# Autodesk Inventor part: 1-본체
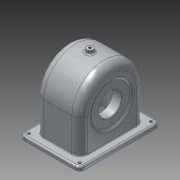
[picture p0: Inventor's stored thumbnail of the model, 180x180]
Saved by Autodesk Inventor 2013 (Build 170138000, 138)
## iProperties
Created: 2016-01
Part Number: 1-본체
Material: 알루미늄 6061
Document SubType Name: Modeling
Designer: Administrator
Density: 2.40731 g/cm^3
Mass: 671.571 g
Surface Area: 997.266 cm^2
Volume: 278.971 cm^3
Author: Administrator
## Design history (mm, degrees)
sketch "스케치1"
  geometry: L1 (-52, 70)-(52, 70); L2 (52, 70)-(52, -70); L3 (52, -70)-(-52, -70); L4 (-52, -70)-(-52, 70); 3 further points
  constraints: 8 end point, 2 midpoint, 2 parallel, 1 horizontal, 1 horizontal alignment, 1 perpendicular, 1 vertical alignment
  dimensions: "d0" = 104 distance between parallel lines of L2 L4; "d2" = 140 distance between parallel lines of L3 L1
extrude "돌출1" new body sketch "스케치1" distance "d3" = 7; taper "d4" = 0 deg
sketch "스케치3"
  geometry: L1 (-38.5, 56)-(38.5, 56); L2 (38.5, 56)-(38.5, -56); L3 (38.5, -56)-(-38.5, -56); L4 (-38.5, -56)-(-38.5, 56); 3 further points
  constraints: 8 end point, 2 midpoint, 2 parallel, 1 horizontal, 1 horizontal alignment, 1 perpendicular, 1 vertical alignment
  dimensions: "d5" = 77 distance between parallel lines of L2 L4; "d7" = 112 distance between parallel lines of L1 L3
extrude "돌출2" join sketch "스케치3" distance "d8" = 114; taper "d9" = 0 deg
fillet "모깎기1" dims "d10" = 56
feature "쉘1" dims "d11" = 7, "d12" = 5
sketch "스케치19"
  geometry: L1 (-38.5, 7)-(-38.5, 65) reference; L2 (-33.5, 0)-(-33.5, 65) reference; L3 (-38.5, 65)-(-38.5, 121) reference; L4 (-33.5, 65)-(-33.5, 116) reference; L5 (-38.5, 60)-(-19.5, 60); L6 (-19.5, 60)-(-19.5, 88); L7 (-19.5, 88)-(-38.5, 103.943); L8 (-52, 0)-(52, 0) reference; L9 (-38.5, 97.416)-(-35.5, 94.899); L10 (-35.5, 94.899)-(-35.5, 60); 1 further point
  constraints: 10 end point, 4 point on line, 3 perpendicular, 1 parallel
  dimensions: "d108" = 56 diameter of L6.end L5; "d111" = 50 deg angle of L7 L6; "d113" = 3 distance between parallel lines of L3 L10; "d114" = 5 distance between parallel lines of L7 L9; "d115" = 16 distance between parallel lines of L10 L6; "d116" = 60 distance from line of L8 L5.start
revolve "회전3" sketch "스케치19" stored, may be unused: angle "d117" = 90 deg
sketch "스케치20"
  geometry: L1 (-38.5, 65)-(-38.5, 121) reference; L2 (-38.5, 7)-(-38.5, 65) reference; L3 (-19.5, 32)-(-19.5, 88) reference; L4 (-33.5, 99.747)-(-19.5, 88) reference; L5 (-38.5, 60)-(-19.5, 60); L6 (-52, 0)-(52, 0) reference; L7 (-38.5, 97.416)-(-35.5, 94.899); L8 (-35.5, 94.899)-(-35.5, 60); 1 further point
  constraints: 6 end point, 3 point on line, 2 perpendicular, 1 midpoint, 1 parallel
  dimensions: "d118" = 60 distance between parallel lines of L6 L5; "d119" = 3 distance between parallel lines of L1 L8; "d120" = 5 distance between parallel lines of L4 L7
revolve "회전4" sketch "스케치20" stored, may be unused: angle "d121" = 90 deg
node "작업 평면1"
sketch "스케치10"
  geometry: C1 r 6 at (0, 0); 1 further point
  constraints: 1 centre point, 1 coincident
  dimensions: "d32" = 12 diameter of C1
extrude "돌출4" join sketch "스케치10" stored distance "d34" = 10; taper "d35" = 0 deg
sketch "스케치14"
  geometry: 2 further points
  constraints: 1 coincident
hole "구멍2" sketch "스케치14" at (0, 0) diameter "d55" = 4.459; stored, may be unused: countersink angle "d59" = 90 deg, drill point angle "d61" = 118 deg; dims "d56" = 7, "d57" = 4, "d58" = 2, "d60" = 9
sketch "스케치16"
  geometry: L1 (52, 70)-(52, -70) reference; L2 (52, -70)-(-52, -70) reference; C1 r 2.5 at (44, -62); 1 further point
  constraints: 1 centre point
  dimensions: "d73" = 8 distance from line of L1 C1.centre; "d74" = 8 distance from line of L2 C1.centre; "d76" = 5 diameter of C1
extrude "돌출7" cut sketch "스케치16" distance "d77" = 16; taper "d78" = 0 deg
fillet "모깎기2" dims "d85" = 14
fillet "모깎기3" dims "d86" = 8
fillet "모깎기4" dims "d87" = 9
fillet "모깎기5" dims "d88" = 3
sketch "스케치17"
  geometry: L1 (-19.5, 65)-(68.5, 65) reference; L2 (63, 0)-(63, 58) reference; 3 further points
  constraints: 1 other
  dimensions: "d92" = 30 distance from line of point (24.5, 35) L1; "d93" = 38.5 distance from line of L2 point (24.5, 35)
feature "엠보싱1" sketch "스케치17" dims "d0" = 104, "d2" = 140, "d11" = 7, "d94" = 0.5, "d95" = 0
sketch "스케치21"
  geometry: C1 r 34.899 at (0, 0) reference; C2 r 20 at (0, 0); 1 further point
  constraints: 1 centre point, 1 coincident
  dimensions: "d122" = 40 diameter of C2
extrude "돌출8" cut sketch "스케치21" distance "d124" = 16; taper "d125" = 0 deg
sketch "스케치22"
  geometry: C1 r 20 at (0, 0) reference; C2 r 34.899 at (0, 0) reference; 2 further points
  constraints: 1 horizontal alignment
  dimensions: "d126" = 28 distance of point (-28, 0) C1.centre
hole "구멍4" sketch "스케치22" at (-28, 0) diameter "d127" = 2.459; stored, may be unused: countersink angle "d131" = 90 deg, drill point angle "d133" = 118 deg; dims "d128" = 7, "d129" = 4, "d130" = 2, "d132" = 9
sketch "스케치23"
  geometry: C1 r 20 at (-5, 0) reference; C2 r 31 at (-5, 0); 1 further point
  constraints: 1 centre point, 1 coincident
  dimensions: "d137" = 62 diameter of C2
extrude "돌출9" join sketch "스케치23" distance "d139" = 10; taper "d140" = 0 deg
sketch "스케치24"
  geometry: C1 r 20 at (0, 0) reference; C2 r 20 at (0, 0); 1 further point
  constraints: 1 centre point, 1 coincident
  dimensions: "d141" = 40 diameter of C2
extrude "돌출10" cut sketch "스케치24" distance "d143" = 15; taper "d144" = 0 deg
sketch "스케치25"
  geometry: C1 r 20 at (0, 0) reference; C2 r 31 at (0, 0) reference; 2 further points
  constraints: 1 horizontal alignment
  dimensions: "d145" = 24 distance of C1.centre point (24, 0)
hole "구멍5" sketch "스케치25" at (24, 0) diameter "d146" = 2.459; stored, may be unused: countersink angle "d150" = 90 deg, drill point angle "d152" = 118 deg; dims "d147" = 6, "d148" = 4, "d149" = 2, "d151" = 8
fillet "모깎기7" dims "d156" = 3
chamfer "모따기2" distance "d157" = 1; stored, may be unused: second distance "d158" = 2, angle "d159" = 45 deg
fillet "모깎기8" dims "d160" = 1
node "솔리드1"
pattern_linear "직사각형 패턴1" dims "d81" = 88, "d84" = 124
pattern_circular "원형 패턴3" dims angle "d135" = 360 deg
pattern_circular "원형 패턴4" dims angle "d154" = 360 deg
node "투영된 루프5"
node "투영된 루프6"
node "투영된 루프7"
other parameters: "d31" = 127
